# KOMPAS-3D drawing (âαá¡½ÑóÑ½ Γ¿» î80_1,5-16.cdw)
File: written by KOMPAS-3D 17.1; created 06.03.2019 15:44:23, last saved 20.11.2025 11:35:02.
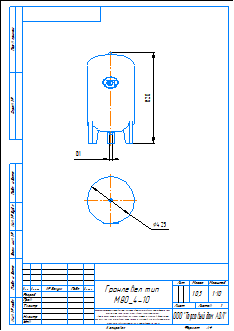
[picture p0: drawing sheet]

Sheet 1: A4, portrait

Title block, sheet 1: name: Гранлевел тип / М80_4-10; mass: 10,5; sheets: 1; sheet format: A4; stored path: C:\Users\kka\KOMPAS_Work\!Trash\ГРАНЛЕВЕЛ тип А Расширительный бак\KOMPAS 2D\Гранлевел тип А100_1,5-16.cdw

Views: Спереди 1, Спереди, Проекционный вид 2
Referenced files in C:\Users\mipv\Desktop\Тип А\SAT\: Гранлевел тип А80_4-10.a3d
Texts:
  kka
  adl
  Гранлевел тип А80_4-10
  Рама для чертежей
  Лит-Масса-Масштаб
  Материал-Предприятие
  Масштаб
  Изм.
  Лист
  № докум.
  Подп.
  Дата
  Лит.
  Разраб.
  Пров.
  Т.контр.
  Листов
  Внимание! Данный продукт является объектом авторского права ООО «Торговый Дом АДЛ».
  Запрещается изменение, копирование, распространение
  (в том числе путем копирования на другие сайты и ресурсы в Интернете)
  или любое иное использование информации и объектов без предварительного
  согласия правообладателя (ООО «Торговый Дом АДЛ»).
  Н.контр.
  Утв.
  ООО "Торговый дом АДЛ"
  Изменение
  Номер документа
  Подпись
  Обозначение документа
  Наименование изделия
  Масса изделия по ГОСТ 2.109-73
  Порядковый номер листа
  Общее количество листов в документе
  Характер работы, выполненной лицом, подписавшим документ
  Наименование или индекс предприятия, выпускающего документ
  Инв. № подл.
  Подп. и дата
  Взам. инв. №
  Инв. № дубл.
  Инвентарный номер подлинника по ГОСТ 2.501-68
  Подпись принявшего подлинник в отдел технической документации
  Инвентарный номер подлинника, взамен которого выпущен данный подлинник
  Инвентарный номер дубликата по ГОСТ 2.502-68
  Подпись принявшего дубликат в отдел технической документации
  Справ. №
  Перв. примен.
  Обозначение документа, взамен или на основании которого выпущен данный документ
  Обозначение документа, в котором впервые записан данный документ
  Подпись лица, копировавшего чертеж
  Обозначение формата листа
  !Рама для чертежа
Dimensions and other numbers on the sheet: 820; 425; 1:10; 1; 10,5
